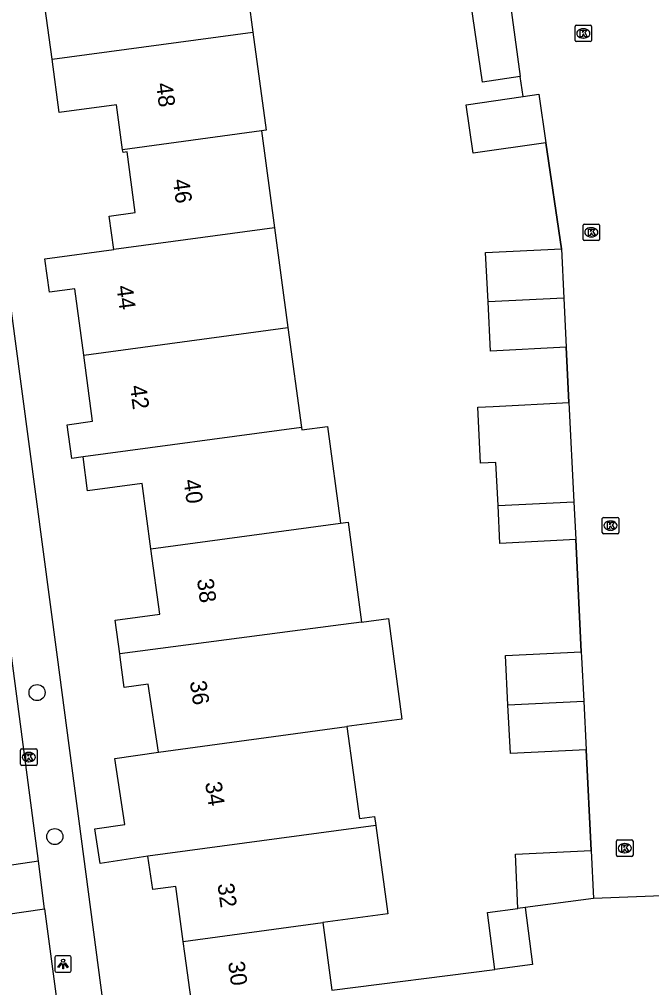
# Model space of a CAD drawing. Extents: x 161084 to 161928, y 385355 to 386522.
# Drawn here: x 161252.7 to 161291, y 385980 to 386038.7 of the extents above; entities that cross this region are included whole.
import ezdxf

# ---------------------------------------------------------------- set-up
doc = ezdxf.new("R2010")
doc.units = 0
for name, color, linetype in [('IMGEO_Boom', 7, 'Continuous'), ('IMGEO_Kolk', 7, 'Continuous'), ('IMGEO_Lichtpunt', 7, 'Continuous'), ('IMGEO_Muur', 7, 'Continuous'), ('IMGEO_Pand', 7, 'Continuous'), ('IMGEO_Pand_nummerreeks', 7, 'Continuous'), ('IMGEO_Rijbaan_lokaal_open', 7, 'Continuous'), ('IMGEO_Voetpad_open', 7, 'Continuous')]:
    doc.layers.add(name, color=color, linetype=linetype)

msp = doc.modelspace()

# ---------------------------------------------------------------- linework, layer by layer
at = {"layer": 'IMGEO_Boom'}
for centre in [(161253.777, 385997.843), (161254.852, 385989.111)]:
    msp.add_circle(centre, 0.489, dxfattribs=at)
at = {"layer": 'IMGEO_Kolk'}
for p, q in [((161286.402, 386037.389), (161286.402, 386038.241)), ((161286.477, 386038.315), (161287.329, 386038.315)), ((161286.89, 386038.095), (161286.915, 386038.095)), ((161287.403, 386038.241), (161287.403, 386037.389)), ((161287.329, 386037.315), (161286.477, 386037.315)), ((161286.913, 386037.535), (161286.888, 386037.535)), ((161286.89, 386025.327), (161286.89, 386026.179)), ((161286.965, 386026.253), (161287.817, 386026.253)), ((161287.378, 386026.033), (161287.403, 386026.033)), ((161287.891, 386026.179), (161287.891, 386025.327)), ((161287.401, 386025.473), (161287.376, 386025.473)), ((161287.817, 386025.253), (161286.965, 386025.253)), ((161288.131, 386008.468), (161288.983, 386008.468)), ((161288.056, 386007.542), (161288.056, 386008.394)), ((161288.544, 386008.248), (161288.569, 386008.248)), ((161289.057, 386008.394), (161289.057, 386007.542)), ((161288.983, 386007.468), (161288.131, 386007.468)), ((161288.567, 386007.688), (161288.542, 386007.688)), ((161252.773, 385993.505), (161252.773, 385994.357)), ((161252.848, 385994.431), (161253.7, 385994.431)), ((161253.774, 385994.357), (161253.774, 385993.505)), ((161253.261, 385994.211), (161253.286, 385994.211)), ((161253.7, 385993.431), (161252.848, 385993.431)), ((161253.284, 385993.651), (161253.259, 385993.651)), ((161288.918, 385987.982), (161288.918, 385988.834)), ((161288.993, 385988.908), (161289.845, 385988.908)), ((161289.406, 385988.688), (161289.431, 385988.688)), ((161289.919, 385988.834), (161289.919, 385987.982)), ((161289.845, 385987.908), (161288.993, 385987.908)), ((161289.429, 385988.128), (161289.404, 385988.128))]:
    msp.add_line(p, q, dxfattribs=at)
for points in [[(161286.402, 386037.389), (161286.402, 386038.241)], [(161286.477, 386038.315), (161287.329, 386038.315)], [(161286.723, 386038.015), (161286.846, 386038.015), (161286.846, 386037.864), (161286.976, 386038.015), (161287.14, 386038.015), (161286.994, 386037.864), (161287.147, 386037.615), (161286.995, 386037.615), (161286.91, 386037.779), (161286.846, 386037.712), (161286.846, 386037.615), (161286.723, 386037.615), (161286.723, 386038.015)], [(161287.403, 386038.241), (161287.403, 386037.389)], [(161287.329, 386037.315), (161286.477, 386037.315)], [(161286.89, 386025.327), (161286.89, 386026.179)], [(161286.965, 386026.253), (161287.817, 386026.253)], [(161287.891, 386026.179), (161287.891, 386025.327)], [(161287.211, 386025.953), (161287.334, 386025.953), (161287.334, 386025.802), (161287.464, 386025.953), (161287.628, 386025.953), (161287.482, 386025.802), (161287.635, 386025.553), (161287.483, 386025.553), (161287.398, 386025.717), (161287.334, 386025.65), (161287.334, 386025.553), (161287.211, 386025.553), (161287.211, 386025.953)], [(161287.817, 386025.253), (161286.965, 386025.253)], [(161288.131, 386008.468), (161288.983, 386008.468)], [(161288.056, 386007.542), (161288.056, 386008.394)], [(161288.377, 386008.168), (161288.5, 386008.168), (161288.5, 386008.017), (161288.63, 386008.168), (161288.794, 386008.168), (161288.648, 386008.017), (161288.801, 386007.768), (161288.649, 386007.768), (161288.564, 386007.932), (161288.5, 386007.865), (161288.5, 386007.768), (161288.377, 386007.768), (161288.377, 386008.168)], [(161289.057, 386008.394), (161289.057, 386007.542)], [(161288.983, 386007.468), (161288.131, 386007.468)], [(161252.773, 385993.505), (161252.773, 385994.357)], [(161252.848, 385994.431), (161253.7, 385994.431)], [(161253.774, 385994.357), (161253.774, 385993.505)], [(161253.094, 385994.131), (161253.217, 385994.131), (161253.217, 385993.98), (161253.347, 385994.131), (161253.511, 385994.131), (161253.365, 385993.98), (161253.518, 385993.731), (161253.366, 385993.731), (161253.281, 385993.895), (161253.217, 385993.828), (161253.217, 385993.731), (161253.094, 385993.731), (161253.094, 385994.131)], [(161253.7, 385993.431), (161252.848, 385993.431)], [(161288.918, 385987.982), (161288.918, 385988.834)], [(161288.993, 385988.908), (161289.845, 385988.908)], [(161289.239, 385988.608), (161289.362, 385988.608), (161289.362, 385988.457), (161289.492, 385988.608), (161289.656, 385988.608), (161289.51, 385988.457), (161289.663, 385988.208), (161289.511, 385988.208), (161289.426, 385988.372), (161289.362, 385988.305), (161289.362, 385988.208), (161289.239, 385988.208), (161289.239, 385988.608)], [(161289.919, 385988.834), (161289.919, 385987.982)], [(161289.845, 385987.908), (161288.993, 385987.908)]]:
    msp.add_lwpolyline(points, dxfattribs=at)
for centre, start, end in [((161286.479, 386038.239), 91.55205, 178.44795), ((161286.479, 386038.239), 91.55205, 178.44795), ((161287.327, 386038.239), 1.55205, 88.44795), ((161287.327, 386038.239), 1.55205, 88.44795), ((161286.479, 386037.391), 181.55205, 268.44795), ((161286.479, 386037.391), 181.55205, 268.44795), ((161287.327, 386037.391), 271.55205, 358.44795), ((161287.327, 386037.391), 271.55205, 358.44795), ((161286.967, 386026.177), 91.55205, 178.44795), ((161286.967, 386026.177), 91.55205, 178.44795), ((161287.815, 386026.177), 1.55205, 88.44795), ((161287.815, 386026.177), 1.55205, 88.44795), ((161286.967, 386025.329), 181.55205, 268.44795), ((161286.967, 386025.329), 181.55205, 268.44795), ((161287.815, 386025.329), 271.55205, 358.44795), ((161287.815, 386025.329), 271.55205, 358.44795), ((161288.133, 386008.392), 91.55205, 178.44795), ((161288.133, 386008.392), 91.55205, 178.44795), ((161288.981, 386008.392), 1.55205, 88.44795), ((161288.981, 386008.392), 1.55205, 88.44795), ((161288.133, 386007.544), 181.55205, 268.44795), ((161288.133, 386007.544), 181.55205, 268.44795), ((161288.981, 386007.544), 271.55205, 358.44795), ((161288.981, 386007.544), 271.55205, 358.44795), ((161252.85, 385994.355), 91.55205, 178.44795), ((161252.85, 385994.355), 91.55205, 178.44795), ((161253.698, 385994.355), 1.55205, 88.44795), ((161253.698, 385994.355), 1.55205, 88.44795), ((161252.85, 385993.507), 181.55205, 268.44795), ((161252.85, 385993.507), 181.55205, 268.44795), ((161253.698, 385993.507), 271.55205, 358.44795), ((161253.698, 385993.507), 271.55205, 358.44795), ((161288.995, 385988.832), 91.55205, 178.44795), ((161288.995, 385988.832), 91.55205, 178.44795), ((161289.843, 385988.832), 1.55205, 88.44795), ((161289.843, 385988.832), 1.55205, 88.44795), ((161288.995, 385987.984), 181.55205, 268.44795), ((161288.995, 385987.984), 181.55205, 268.44795), ((161289.843, 385987.984), 271.55205, 358.44795), ((161289.843, 385987.984), 271.55205, 358.44795)]:
    msp.add_arc(centre, 0.0765, start, end, dxfattribs=at)
for centre, major_axis, ratio, start_param, end_param in [((161286.889, 386037.815), (-0.387, 0.002), 0.722429, 4.712389, 7.853982), ((161286.914, 386037.815), (-0.39, 0.002), 0.717154, 1.570796, 4.712389), ((161287.377, 386025.753), (-0.387, 0.002), 0.722429, 4.712389, 7.853982), ((161287.402, 386025.753), (-0.39, 0.002), 0.717154, 1.570796, 4.712389), ((161288.543, 386007.968), (-0.387, 0.002), 0.722429, 4.712389, 7.853982), ((161288.568, 386007.968), (-0.39, 0.002), 0.717154, 1.570796, 4.712389), ((161253.26, 385993.931), (-0.387, 0.002), 0.722429, 4.712389, 7.853982), ((161253.285, 385993.931), (-0.39, 0.002), 0.717154, 1.570796, 4.712389), ((161289.405, 385988.408), (-0.387, 0.002), 0.722429, 4.712389, 7.853982), ((161289.43, 385988.408), (-0.39, 0.002), 0.717154, 1.570796, 4.712389)]:
    msp.add_ellipse(centre, major_axis=major_axis, ratio=ratio, start_param=start_param, end_param=end_param, dxfattribs=at)
at = {"layer": 'IMGEO_Lichtpunt'}
for p, q in [((161254.855, 385981.79), (161254.855, 385980.983)), ((161254.855, 385981.79), (161254.855, 385980.983)), ((161255.757, 385981.885), (161254.949, 385981.885)), ((161255.757, 385981.885), (161254.949, 385981.885)), ((161255.851, 385980.983), (161255.851, 385981.79)), ((161255.851, 385980.983), (161255.851, 385981.79)), ((161254.949, 385980.889), (161255.757, 385980.889)), ((161254.949, 385980.889), (161255.757, 385980.889))]:
    msp.add_line(p, q, dxfattribs=at)
for points in [[(161255.229, 385981.454), (161255.268, 385981.426), (161255.08, 385981.164), (161255.042, 385981.191), (161255.229, 385981.454)], [(161255.331, 385981.406), (161255.378, 385981.406), (161255.378, 385981.084), (161255.331, 385981.084), (161255.331, 385981.406)], [(161255.441, 385981.426), (161255.479, 385981.453), (161255.666, 385981.191), (161255.627, 385981.163), (161255.441, 385981.426)]]:
    msp.add_lwpolyline(points, dxfattribs=at)
msp.add_circle((161255.354, 385981.588), 0.0994, dxfattribs=at)
for centre, start, end in [((161254.949, 385981.79), 90, 180), ((161254.949, 385981.79), 90, 180), ((161255.757, 385981.79), 0, 90), ((161255.757, 385981.79), 0, 90), ((161254.949, 385980.983), 180, 270), ((161254.949, 385980.983), 180, 270), ((161255.757, 385980.983), 270, 0), ((161255.757, 385980.983), 270, 360)]:
    msp.add_arc(centre, 0.0946, start, end, dxfattribs=at)
at = {"layer": 'IMGEO_Muur'}
for points in [[(161284.638, 386031.186), (161285.575, 386024.751)], [(161285.869, 386018.78), (161286.035, 386015.424)], [(161286.445, 386007.118), (161286.781, 386000.32)], [(161287.075, 385994.375), (161287.377, 385988.266)]]:
    msp.add_lwpolyline(points, dxfattribs=at)
at = {"layer": 'IMGEO_Pand'}
for points in [[(161266.064, 386043.842), (161266.868, 386037.893)], [(161254.682, 386036.245), (161254.246, 386039.47), (161257.745, 386039.943), (161257.377, 386042.668)], [(161283.083, 386035.197), (161280.787, 386034.862), (161280.085, 386039.681)], [(161282.425, 386039.997), (161283.083, 386035.197)], [(161254.682, 386036.245), (161266.868, 386037.893)], [(161266.868, 386037.893), (161267.673, 386031.937), (161267.38, 386031.898)], [(161258.967, 386030.76), (161258.598, 386033.492), (161255.118, 386033.021), (161254.682, 386036.245)], [(161284.638, 386031.186), (161280.22, 386030.543), (161279.792, 386033.482), (161283.25, 386033.985)], [(161283.25, 386033.985), (161284.21, 386034.125), (161284.638, 386031.186)], [(161267.38, 386031.898), (161258.967, 386030.76)], [(161267.38, 386031.898), (161268.174, 386026.027)], [(161258.422, 386024.709), (161258.148, 386026.74), (161259.729, 386026.954), (161259.233, 386030.627), (161258.989, 386030.595), (161258.967, 386030.76)], [(161268.174, 386026.027), (161258.422, 386024.709)], [(161268.174, 386026.027), (161268.991, 386019.985)], [(161256.605, 386018.31), (161256.063, 386022.323), (161254.526, 386022.115), (161254.251, 386024.146), (161258.422, 386024.709)], [(161281.129, 386021.54), (161280.982, 386024.524), (161285.575, 386024.751)], [(161285.575, 386024.751), (161285.722, 386021.767)], [(161285.722, 386021.767), (161281.129, 386021.54)], [(161285.869, 386018.78), (161281.276, 386018.553), (161281.129, 386021.54)], [(161285.722, 386021.767), (161285.869, 386018.78)], [(161256.605, 386018.31), (161268.991, 386019.985)], [(161268.991, 386019.985), (161269.81, 386013.922)], [(161256.566, 386012.13), (161255.888, 386012.038), (161255.611, 386014.089), (161257.147, 386014.296), (161256.605, 386018.31)], [(161281.739, 386009.179), (161281.609, 386011.795), (161280.666, 386011.748), (161280.498, 386015.15), (161281.442, 386015.197), (161286.035, 386015.424)], [(161286.035, 386015.424), (161286.332, 386009.404)], [(161269.81, 386013.922), (161256.566, 386012.13)], [(161269.81, 386013.922), (161269.831, 386013.768), (161271.391, 386013.979), (161272.183, 386008.115)], [(161260.679, 386006.56), (161260.144, 386010.521), (161256.844, 386010.074), (161256.566, 386012.13)], [(161281.739, 386009.179), (161286.332, 386009.404)], [(161286.445, 386007.118), (161281.852, 386006.891), (161281.739, 386009.179)], [(161286.332, 386009.404), (161286.445, 386007.118)], [(161260.679, 386006.56), (161272.183, 386008.115)], [(161272.183, 386008.115), (161272.643, 386008.177), (161273.462, 386002.121)], [(161258.789, 386000.192), (161258.513, 386002.235), (161261.214, 386002.6), (161260.679, 386006.56)], [(161273.462, 386002.121), (161271.743, 386001.888), (161258.789, 386000.192)], [(161273.462, 386002.121), (161275.081, 386002.34), (161275.906, 385996.237), (161272.568, 385995.786)], [(161261.132, 385994.24), (161260.509, 385998.348), (161259.065, 385998.152), (161258.815, 386000), (161258.789, 386000.192)], [(161282.336, 385997.098), (161282.188, 386000.093), (161286.781, 386000.32)], [(161286.781, 386000.32), (161286.797, 386000), (161286.929, 385997.322)], [(161282.336, 385997.098), (161286.929, 385997.322)], [(161286.929, 385997.322), (161287.075, 385994.375)], [(161287.075, 385994.375), (161282.482, 385994.148), (161282.336, 385997.098)], [(161261.132, 385994.24), (161272.568, 385995.786)], [(161272.568, 385995.786), (161273.322, 385990.213), (161274.249, 385990.338), (161274.324, 385989.785)], [(161260.496, 385987.915), (161257.604, 385987.478), (161257.287, 385989.573), (161259.093, 385989.847), (161258.488, 385993.837), (161261.132, 385994.24)], [(161274.324, 385989.785), (161260.496, 385987.915)], [(161274.324, 385989.785), (161275.048, 385984.434), (161271.108, 385983.9)], [(161262.642, 385982.755), (161262.191, 385986.089), (161260.801, 385985.9), (161260.496, 385987.915)], [(161282.94, 385984.753), (161282.784, 385988.039), (161287.377, 385988.266)], [(161287.377, 385988.266), (161287.514, 385985.354)], [(161287.514, 385985.354), (161283.374, 385984.81)], [(161281.543, 385981.053), (161281.089, 385984.51), (161282.94, 385984.753)], [(161283.374, 385984.81), (161283.827, 385981.353), (161281.543, 385981.053)], [(161283.374, 385984.81), (161282.94, 385984.753)], [(161262.642, 385982.755), (161271.108, 385983.9)], [(161271.108, 385983.9), (161271.663, 385979.794)], [(161263.197, 385978.649), (161262.74, 385982.028), (161262.642, 385982.755)]]:
    msp.add_lwpolyline(points, dxfattribs=at)
at = {"layer": 'IMGEO_Rijbaan_lokaal_open'}
for points in [[(161283.25, 386033.985), (161283.083, 386035.197)], [(161285.575, 386024.751), (161284.638, 386031.186)], [(161253.859, 385987.625), (161252.249, 385999.936), (161249.423, 386021.68)], [(161286.035, 386015.424), (161285.869, 386018.78)], [(161286.781, 386000.32), (161286.445, 386007.118)], [(161287.377, 385988.266), (161287.075, 385994.375)], [(161253.859, 385987.625), (161247.029, 385986.607)], [(161254.228, 385984.726), (161253.859, 385987.625)], [(161294.301, 385985.614), (161287.514, 385985.354)], [(161247.399, 385983.749), (161254.228, 385984.726)], [(161254.228, 385984.726), (161255.872, 385972.432), (161257.488, 385960.285), (161258.183, 385954.37), (161258.973, 385948.652), (161259.437, 385945.421), (161260.18, 385939.559), (161260.642, 385935.92), (161262.973, 385917.539), (161263.934, 385910.799), (161267.007, 385887.426)]]:
    msp.add_lwpolyline(points, dxfattribs=at)
at = {"layer": 'IMGEO_Voetpad_open'}
for points in [[(161235.653, 386146.984), (161252.413, 386019.447), (161255.001, 386000), (161257.909, 385977.952)], [(161271.663, 385979.794), (161281.543, 385981.053)]]:
    msp.add_lwpolyline(points, dxfattribs=at)

# ---------------------------------------------------------------- texts
at = {"layer": 'IMGEO_Pand_nummerreeks'}
for s, rotation, p in [('48', 277.37949, (161260.989, 386034.767)), ('46', 277.68888, (161262.005, 386028.931)), ('44', 277.69094, (161258.584, 386022.483)), ('42', 277.69094, (161259.402, 386016.432)), ('40', 277.69317, (161262.66, 386010.721)), ('38', 277.69317, (161263.472, 386004.705)), ('36', 278.61707, (161263.035, 385998.502)), ('34', 278.61936, (161263.962, 385992.377)), ('32', 277.70055, (161264.715, 385986.227)), ('30', 277.70055, (161265.355, 385981.492))]:
    msp.add_text(s, height=1, rotation=rotation, dxfattribs=at).set_placement(p)

doc.saveas('drawing.dxf')
